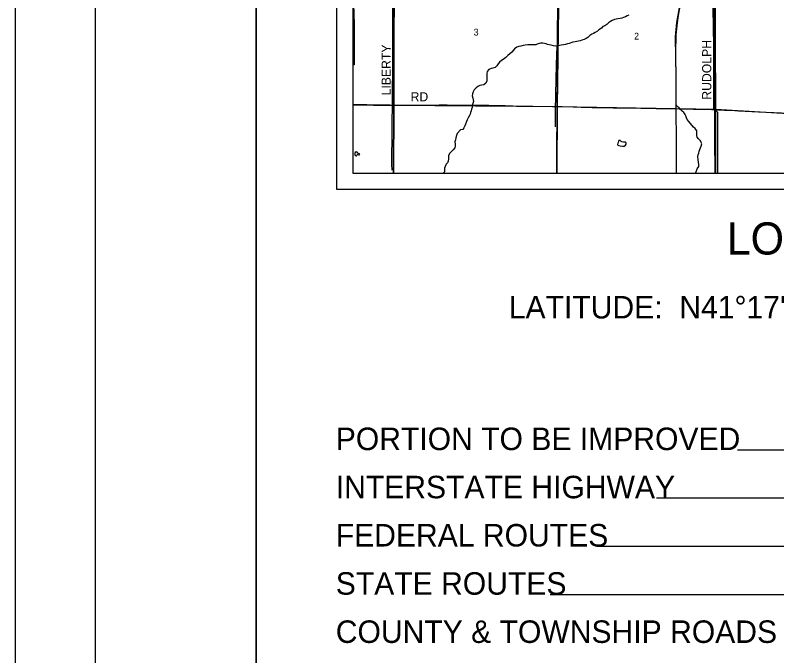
# Model space of a CAD drawing. Extents: x 0 to 39.4, y 0 to 22.
# Drawn here: x 0 to 4.739, y 11.097 to 15.083 of the extents above; entities that cross this region are included whole.
import ezdxf

# ---------------------------------------------------------------- set-up
doc = ezdxf.new("R2010")
doc.units = 0
for name, color, linetype in [('Default', 7, 'Continuous'), ('GM_X_County_Road', 7, 'Continuous'), ('GM_X_County_Road_Text', 7, 'Continuous'), ('GM_X_Interstate_Route', 7, 'Continuous'), ('GM_X_Minor_Lake', 7, 'Continuous'), ('GM_X_Minor_River', 7, 'Continuous'), ('GM_X_Rail_Line', 7, 'Continuous'), ('GM_X_Section', 7, 'Continuous'), ('GM_X_Section_Text', 7, 'Continuous'), ('GM_X_Township_Road', 7, 'Continuous'), ('GM_X_Township_Road_Text', 7, 'Continuous'), ('SH_Border', 7, 'Continuous'), ('SH_Cut_Line', 7, 'Continuous'), ('SH_Data', 7, 'Continuous'), ('SH_Text', 7, 'Continuous')]:
    doc.layers.add(name, color=color, linetype=linetype)

msp = doc.modelspace()

# ---------------------------------------------------------------- linework, layer by layer
at = {"layer": 'Default'}
for points in [[(2.1, 15.5089), (2.1, 14.5256), (2.3556, 14.5215), (2.3597, 15.4744), (2.3594, 15.5066)], [(2.1, 14.5256), (2.1, 14.1), (2.353, 14.1), (2.3556, 14.5215)], [(2.353, 14.1), (3.3698, 14.1), (3.3725, 14.5132), (2.3556, 14.5215)], [(3.3698, 14.1), (4.3575, 14.1), (4.3571, 14.4954), (3.3725, 14.5132)], [(4.3575, 14.1), (5.3634, 14.1), (5.3657, 14.4352), (4.3571, 14.4954)]]:
    msp.add_lwpolyline(points, close=True, dxfattribs=at)
at = {"layer": 'GM_X_County_Road'}
for points in [[(2.3571, 14.5167), (2.3571, 14.5187), (2.3571, 14.5241), (2.3577, 14.6523), (2.3578, 14.7331), (2.3581, 14.8015), (2.3581, 14.8575), (2.3583, 14.9196), (2.3583, 14.988), (2.3587, 15.0315), (2.3602, 15.1061), (2.361, 15.1714), (2.3611, 15.2087), (2.3615, 15.2988), (2.3622, 15.3796), (2.3622, 15.4324), (2.3625, 15.4698)], [(2.1, 14.5303), (2.1879, 14.528), (2.275, 14.5259), (2.3309, 14.5244), (2.3527, 14.5241), (2.3571, 14.5241)], [(2.3553, 14.1), (2.3554, 14.1115), (2.3553, 14.1519), (2.3561, 14.2079), (2.3565, 14.2514), (2.3565, 14.27), (2.3561, 14.3166), (2.3567, 14.3757), (2.3566, 14.4161), (2.3567, 14.4472), (2.3571, 14.5167)], [(2.3571, 14.5241), (2.3868, 14.5239), (2.5858, 14.5242), (2.6386, 14.5245), (2.6883, 14.5243), (2.7878, 14.5241), (2.8375, 14.5241), (2.8717, 14.5238), (2.9463, 14.5227), (2.9898, 14.5219), (3.0488, 14.5209), (3.0954, 14.5199), (3.2197, 14.5175), (3.344, 14.515), (3.3732, 14.5144)], [(3.3732, 14.5144), (3.4031, 14.5139), (3.4714, 14.5122), (3.5212, 14.5112), (3.5895, 14.5095), (3.661, 14.5082), (3.72, 14.5074), (3.7636, 14.507), (3.7977, 14.5062), (3.9873, 14.5032), (4.0774, 14.502), (4.1054, 14.5016), (4.1303, 14.5012), (4.18, 14.5003), (4.2203, 14.4989), (4.3322, 14.4955), (4.3528, 14.4954)], [(4.3528, 14.4954), (4.354, 14.4954), (4.3695, 14.495), (4.4129, 14.4928), (4.4533, 14.4912), (4.4998, 14.4886), (4.624, 14.4826), (4.8165, 14.4733), (4.9314, 14.4674), (5.0151, 14.4626), (5.0462, 14.4607), (5.0742, 14.4592)]]:
    msp.add_lwpolyline(points, dxfattribs=at)
at = {"layer": 'GM_X_Interstate_Route'}
msp.add_lwpolyline([(2.1, 15.507), (2.1, 14.1), (5.3613, 14.1), (5.3656, 14.4414), (5.3638, 14.6746), (5.3629, 14.7948), (5.3615, 14.845), (5.3635, 14.9304), (5.3699, 15.3511)], dxfattribs=at)
at = {"layer": 'GM_X_Minor_Lake'}
for p, q in [((3.7513, 14.2918), (3.7493, 14.2867)), ((2.1126, 14.2221), (2.1131, 14.2166))]:
    msp.add_line(p, q, dxfattribs=at)
for points in [[(3.7493, 14.2867), (3.7489, 14.2858), (3.7466, 14.2794), (3.7499, 14.2748), (3.7548, 14.272), (3.7646, 14.2696), (3.7782, 14.2679), (3.7889, 14.2685), (3.7977, 14.2733), (3.8012, 14.2797), (3.8005, 14.2888), (3.7961, 14.2927), (3.7847, 14.2933), (3.7752, 14.296), (3.77, 14.298), (3.7632, 14.3023), (3.7564, 14.3032), (3.7537, 14.2983), (3.7513, 14.2918)], [(2.1131, 14.2166), (2.1141, 14.212), (2.1164, 14.2101), (2.1194, 14.2078), (2.1228, 14.2089), (2.1259, 14.2122), (2.129, 14.2156), (2.1327, 14.2152), (2.1365, 14.2147), (2.14, 14.2151), (2.1434, 14.2169), (2.1415, 14.22), (2.1351, 14.222), (2.1318, 14.2247), (2.1273, 14.2305), (2.1216, 14.2321), (2.1159, 14.2291), (2.1126, 14.2221)]]:
    msp.add_lwpolyline(points, dxfattribs=at)
at = {"layer": 'GM_X_Minor_River'}
for points in [[(2.1038, 15.153), (2.1096, 15.0244), (2.1096, 14.7743), (2.1, 14.7744)], [(2.3465, 15.1503), (2.3471, 14.7796), (2.3418, 14.1563), (2.3426, 14.1179)], [(4.1121, 14.5272), (4.1125, 14.6746), (4.1113, 14.8514), (4.1132, 14.9612), (4.1186, 15.0167), (4.125, 15.0676), (4.133, 15.117), (4.136, 15.1265)], [(4.3407, 15.1266), (4.3454, 14.8897), (4.3451, 14.5686), (4.3451, 14.5043), (4.3705, 14.48), (4.3697, 14.3451), (4.3703, 14.1)], [(3.8173, 15.084), (3.8078, 15.0795), (3.798, 15.0738), (3.7858, 15.0685), (3.7752, 15.065), (3.7638, 15.0616), (3.7505, 15.0597), (3.7384, 15.0578), (3.7285, 15.0556), (3.7152, 15.051), (3.7031, 15.043), (3.6925, 15.035), (3.6819, 15.0259), (3.6686, 15.0172), (3.6572, 15.0122), (3.6469, 15.0024), (3.6322, 14.9914), (3.6223, 14.9834), (3.6075, 14.9754), (3.598, 14.9697), (3.5885, 14.9648), (3.576, 14.9564), (3.5631, 14.9446), (3.5521, 14.9382), (3.5392, 14.9325), (3.5252, 14.9275), (3.5153, 14.9245), (3.5039, 14.9222), (3.4941, 14.9199), (3.4838, 14.9181), (3.4694, 14.9146), (3.4459, 14.9078), (3.436, 14.9055), (3.4239, 14.9017), (3.4106, 14.8995), (3.3965, 14.8968), (3.3867, 14.8945), (3.3742, 14.8922), (3.3613, 14.8907), (3.3487, 14.8923), (3.3355, 14.8957), (3.3233, 14.8995), (3.3127, 14.901), (3.3032, 14.9048), (3.2926, 14.9071), (3.2831, 14.9082), (3.271, 14.909), (3.2596, 14.906), (3.2482, 14.9022), (3.2383, 14.8988), (3.2254, 14.8984), (3.2129, 14.8991), (3.2, 14.8995), (3.1894, 14.8991), (3.1738, 14.8965), (3.1606, 14.8935), (3.1462, 14.8904), (3.1344, 14.8874), (3.1211, 14.8832), (3.1075, 14.8737), (3.0983, 14.8635), (3.09, 14.8536), (3.0782, 14.8426), (3.0657, 14.8315), (3.0524, 14.8201), (3.0365, 14.808), (3.0266, 14.8008), (3.0137, 14.7901), (3.0043, 14.781), (2.9959, 14.7688), (2.9853, 14.7586), (2.972, 14.7536), (2.9614, 14.7517), (2.9462, 14.7453), (2.9356, 14.7331), (2.9348, 14.7206), (2.9348, 14.7111), (2.9344, 14.7012), (2.9348, 14.6883), (2.9348, 14.675), (2.9276, 14.6602), (2.9155, 14.6495), (2.9011, 14.6472), (2.8916, 14.6465), (2.879, 14.6393), (2.8688, 14.6301), (2.8559, 14.6184), (2.8498, 14.6062), (2.8453, 14.594), (2.8441, 14.5811), (2.8464, 14.5674), (2.8495, 14.5564), (2.8506, 14.5465), (2.8468, 14.5336), (2.8441, 14.5211), (2.8422, 14.5082), (2.84, 14.4979)], [(3.3696, 14.8917), (3.3662, 14.7744), (3.3609, 14.5897), (3.3586, 14.4886), (3.359, 14.3875)], [(4.2337, 14.1), (4.2358, 14.1038), (4.2384, 14.1136), (4.2422, 14.1273), (4.2529, 14.1414), (4.254, 14.1539), (4.2521, 14.168), (4.2487, 14.1836), (4.2479, 14.2033), (4.2494, 14.2144), (4.2529, 14.2246), (4.2559, 14.236), (4.2593, 14.2474), (4.2642, 14.2573), (4.2684, 14.2672), (4.2722, 14.2816), (4.2688, 14.2911), (4.2631, 14.3006), (4.2517, 14.3139), (4.2441, 14.3238), (4.2403, 14.3352), (4.2403, 14.3493), (4.2407, 14.363), (4.2309, 14.377), (4.2214, 14.3854), (4.2123, 14.3972), (4.2005, 14.4105), (4.191, 14.4223), (4.1811, 14.4344), (4.1762, 14.4443), (4.172, 14.4565), (4.1675, 14.466), (4.1595, 14.477), (4.15, 14.4854), (4.1387, 14.4971), (4.1311, 14.5066), (4.1182, 14.5154), (4.1121, 14.5272)], [(2.84, 14.4979), (2.8366, 14.488), (2.8335, 14.4781), (2.8301, 14.4675), (2.8256, 14.458), (2.8183, 14.4451), (2.8115, 14.4314), (2.8077, 14.4215), (2.8016, 14.4052), (2.7982, 14.3945), (2.7922, 14.3831), (2.7857, 14.3713), (2.7709, 14.3698), (2.7497, 14.3474), (2.7455, 14.3352), (2.7413, 14.3208), (2.739, 14.3075), (2.736, 14.2942), (2.7364, 14.2801), (2.7368, 14.2699), (2.7356, 14.2577), (2.7258, 14.2448), (2.7148, 14.2357), (2.7034, 14.2243), (2.6969, 14.211), (2.6954, 14.1992), (2.6958, 14.1885), (2.6931, 14.1749), (2.689, 14.165), (2.6818, 14.1555), (2.6742, 14.1418), (2.6719, 14.1308), (2.6715, 14.1182), (2.6707, 14.1087), (2.6636, 14.1)]]:
    msp.add_lwpolyline(points, dxfattribs=at)
at = {"layer": 'GM_X_Rail_Line'}
msp.add_lwpolyline([(4.1313, 15.1291), (4.1146, 15.0383), (4.1063, 14.9476), (4.1106, 14.6977), (4.113, 14.1)], dxfattribs=at)
at = {"layer": 'GM_X_Section'}
for points in [[(2.3597, 15.4744), (3.3623, 15.4472), (3.3836, 15.4465), (3.3725, 14.5132), (2.3556, 14.5215)], [(3.3836, 15.4465), (4.3536, 15.4159), (4.3571, 14.4954), (3.3725, 14.5132)], [(4.3536, 15.4159), (4.3695, 15.415), (5.3717, 15.3889), (5.3657, 14.4352), (4.3571, 14.4954)]]:
    msp.add_lwpolyline(points, close=True, dxfattribs=at)
at = {"layer": 'GM_X_Township_Road'}
for points in [[(3.3732, 14.5144), (3.373, 14.5663), (3.3734, 14.644), (3.374, 14.7746), (3.3743, 14.871), (3.3746, 14.9083), (3.3748, 14.9611), (3.3765, 15.1414), (3.378, 15.3062), (3.3781, 15.3652), (3.3782, 15.4336), (3.3782, 15.4403)], [(4.3528, 14.4954), (4.3532, 14.5012), (4.3534, 14.517), (4.3537, 14.5605), (4.3531, 14.6942), (4.3525, 14.8962), (4.3523, 14.9584), (4.3517, 15.1262), (4.3517, 15.2537), (4.3515, 15.3656), (4.3518, 15.3842), (4.3528, 15.3947), (4.3537, 15.3991), (4.3549, 15.4028), (4.3582, 15.4087)], [(3.3691, 14.1), (3.3695, 14.1622), (3.37, 14.2119), (3.3701, 14.243), (3.3709, 14.327), (3.3713, 14.3923), (3.3719, 14.4762), (3.3727, 14.498), (3.3732, 14.5135), (3.3732, 14.5144)], [(4.3554, 14.1), (4.355, 14.1472), (4.354, 14.2684), (4.3529, 14.3648), (4.3521, 14.4269), (4.3521, 14.4549), (4.3521, 14.4736), (4.3526, 14.4887), (4.3528, 14.4954)]]:
    msp.add_lwpolyline(points, dxfattribs=at)
at = {"layer": 'SH_Border'}
for points in [[(0.5, 21.5), (1.5, 21.5), (1.5, 0.5), (0.5, 0.5)], [(1.5, 21.5), (33.5, 21.5), (33.5, 0.5), (1.5, 0.5)]]:
    msp.add_lwpolyline(points, close=True, dxfattribs=at)
at = {"layer": 'SH_Cut_Line'}
msp.add_lwpolyline([(0, 0), (34, 0), (34, 22), (0, 22)], close=True, dxfattribs=at)
at = {"layer": 'SH_Data'}
for p, q in [((2, 21), (2, 14)), ((2.1, 20.9), (2.1, 14.1)), ((2.1, 14.1), (8.9, 14.1)), ((2.1, 14.1), (2.1, 14.1)), ((2, 14), (9, 14)), ((7.7, 12.3767), (4.4937, 12.3767)), ((7.7, 12.0767), (3.9895, 12.0767)), ((7.7, 11.7767), (3.6192, 11.7767)), ((7.7, 11.4767), (3.3288, 11.4767))]:
    msp.add_line(p, q, dxfattribs=at)

# ---------------------------------------------------------------- texts
at = {"layer": 'GM_X_County_Road_Text'}
for s, rotation, p in [('LIBERTY', 89.8379, (2.336, 14.5839)), ('RD', 0, (2.4601, 14.5471))]:
    msp.add_text(s, height=0.05682, rotation=rotation, dxfattribs=at).set_placement(p)
at = {"layer": 'GM_X_Section_Text'}
for s, p in [('3', (2.8522, 14.9565)), ('2', (3.8505, 14.9318))]:
    msp.add_text(s, height=0.0419, rotation=0, dxfattribs=at).set_placement(p)
at = {"layer": 'GM_X_Township_Road_Text'}
msp.add_text('RUDOLPH', height=0.05682, rotation=90, dxfattribs=at).set_placement((4.331, 14.5573))
at = {"layer": 'SH_Text'}
for s, height, p in [('LOCATION MAP', 0.2, (4.4269, 13.5938)), ('LATITUDE:  N41°17\'00"     LONGITUDE:  W83°39\'10"', 0.14, (3.071, 13.1959)), ('PORTION TO BE IMPROVED', 0.14, (1.9944, 12.3767)), ('INTERSTATE HIGHWAY', 0.14, (1.9944, 12.0767)), ('FEDERAL ROUTES', 0.14, (1.9944, 11.7767)), ('STATE ROUTES', 0.14, (1.9944, 11.4767)), ('COUNTY & TOWNSHIP ROADS', 0.14, (1.9944, 11.1767))]:
    msp.add_text(s, height=height, dxfattribs=at).set_placement(p)

doc.saveas('drawing.dxf')
